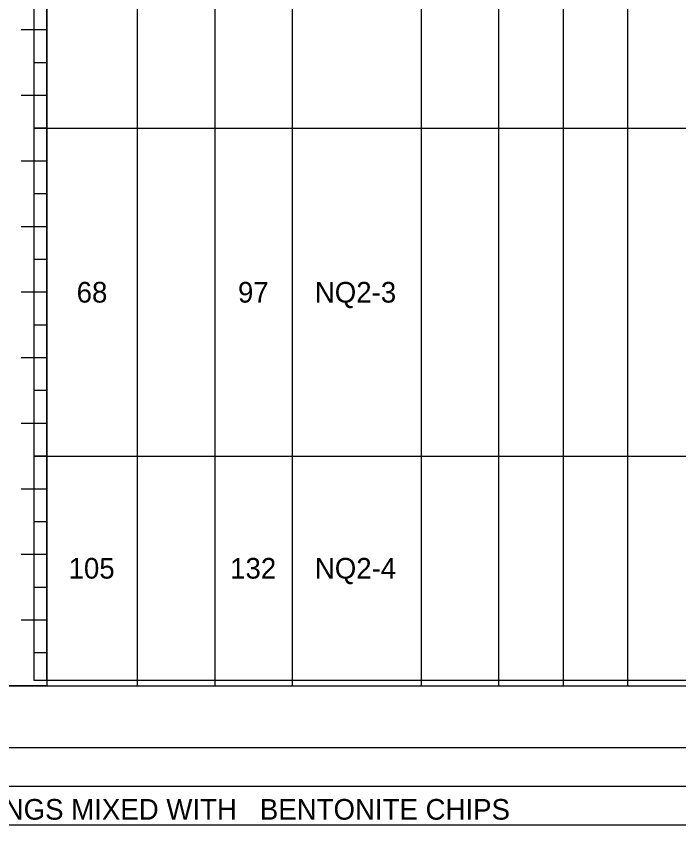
# Model space of a CAD drawing. Extents: x 0 to 0.833, y -0.32 to 0.608.
# Drawn here: x 0.4026 to 0.6165, y -0.32 to -0.0591 of the extents above; entities that cross this region are included whole.
import ezdxf

# ---------------------------------------------------------------- set-up
doc = ezdxf.new("R2010")
doc.units = 0

msp = doc.modelspace()

# ---------------------------------------------------------------- linework, layer by layer
for points in [[(0, -0.32004), (0.83333, -0.32004), (0.83333, 0.60833), (0, 0.60833)], [(0.40833, -0.09525), (0.4125, -0.09525), (0.4125, 0.01058), (0.40833, 0.01058)], [(0.40833, -0.20108), (0.4125, -0.20108), (0.4125, -0.09525), (0.40833, -0.09525)], [(0.40833, -0.2734), (0.4125, -0.2734), (0.4125, -0.20108), (0.40833, -0.20108)]]:
    msp.add_lwpolyline(points, close=True)
for points in [[(0.4125, 0.55417), (0.4125, -0.27517)], [(0.4125, 0.55417), (0.4125, -0.27517)], [(0.44167, 0.55417), (0.44167, -0.27517)], [(0.46667, 0.55417), (0.46667, -0.27517)], [(0.49167, 0.55417), (0.49167, -0.27517)], [(0.53333, 0.55417), (0.53333, -0.27517)], [(0.55833, 0.55417), (0.55833, -0.27517)], [(0.57917, 0.54167), (0.57917, -0.27517)], [(0.6, 0.54167), (0.6, -0.27517)], [(0.40833, 0.01058), (0.40833, -0.09525)], [(0.4125, -0.0635), (0.40417, -0.0635)], [(0.4125, -0.0635), (0.40833, -0.0635)], [(0.4125, -0.07408), (0.40833, -0.07408)], [(0.4125, -0.08467), (0.40417, -0.08467)], [(0.4125, -0.08467), (0.40833, -0.08467)], [(0.40833, -0.09525), (0.4125, -0.09525)], [(0.40833, -0.09525), (0.40833, -0.20108)], [(0.40833, -0.09525), (0.4125, -0.09525)], [(0.4125, -0.09525), (0.40833, -0.09525)], [(0.4125, -0.09525), (0.44167, -0.09525)], [(0.44167, -0.09525), (0.46667, -0.09525)], [(0.46667, -0.09525), (0.49167, -0.09525)], [(0.49167, -0.09525), (0.53333, -0.09525)], [(0.53333, -0.09525), (0.55833, -0.09525)], [(0.55833, -0.09525), (0.57917, -0.09525)], [(0.57917, -0.09525), (0.6, -0.09525)], [(0.6, -0.09525), (0.62083, -0.09525)], [(0.4125, -0.10583), (0.40417, -0.10583)], [(0.4125, -0.10583), (0.40833, -0.10583)], [(0.4125, -0.11642), (0.40833, -0.11642)], [(0.4125, -0.127), (0.40417, -0.127)], [(0.4125, -0.127), (0.40833, -0.127)], [(0.4125, -0.13758), (0.40833, -0.13758)], [(0.4125, -0.14817), (0.40417, -0.14817)], [(0.4125, -0.14817), (0.40833, -0.14817)], [(0.4125, -0.15875), (0.40833, -0.15875)], [(0.4125, -0.16933), (0.40417, -0.16933)], [(0.4125, -0.16933), (0.40833, -0.16933)], [(0.4125, -0.17992), (0.40833, -0.17992)], [(0.4125, -0.1905), (0.40417, -0.1905)], [(0.4125, -0.1905), (0.40833, -0.1905)], [(0.40833, -0.20108), (0.4125, -0.20108)], [(0.40833, -0.20108), (0.40833, -0.2734)], [(0.40833, -0.20108), (0.4125, -0.20108)], [(0.4125, -0.20108), (0.40833, -0.20108)], [(0.4125, -0.20108), (0.44167, -0.20108)], [(0.44167, -0.20108), (0.46667, -0.20108)], [(0.46667, -0.20108), (0.49167, -0.20108)], [(0.49167, -0.20108), (0.53333, -0.20108)], [(0.53333, -0.20108), (0.55833, -0.20108)], [(0.55833, -0.20108), (0.57917, -0.20108)], [(0.57917, -0.20108), (0.6, -0.20108)], [(0.6, -0.20108), (0.62083, -0.20108)], [(0, -0.20754), (0, -0.32004), (0.83333, -0.32004), (0.83333, -0.20754)], [(0.4125, -0.21167), (0.40417, -0.21167)], [(0.4125, -0.21167), (0.40833, -0.21167)], [(0.4125, -0.22225), (0.40833, -0.22225)], [(0.4125, -0.23283), (0.40417, -0.23283)], [(0.4125, -0.23283), (0.40833, -0.23283)], [(0.4125, -0.24342), (0.40833, -0.24342)], [(0.4125, -0.254), (0.40417, -0.254)], [(0.4125, -0.254), (0.40833, -0.254)], [(0.4125, -0.26458), (0.40833, -0.26458)], [(0.40833, -0.2734), (0.4125, -0.2734)], [(0.4125, -0.2734), (0.44167, -0.2734)], [(0.44167, -0.2734), (0.46667, -0.2734)], [(0.46667, -0.2734), (0.49167, -0.2734)], [(0.49167, -0.2734), (0.53333, -0.2734)], [(0.53333, -0.2734), (0.55833, -0.2734)], [(0.55833, -0.2734), (0.57917, -0.2734)], [(0.57917, -0.2734), (0.6, -0.2734)], [(0.6, -0.2734), (0.62083, -0.2734)], [(0.37917, -0.27517), (0.4125, -0.27517)], [(0.4125, -0.27517), (0.39583, -0.27517)], [(0.4125, -0.27517), (0.40417, -0.27517)], [(0.40833, -0.27517), (0.4125, -0.27517)], [(0.4125, -0.27517), (0.40833, -0.27517)], [(0.4125, -0.27517), (0.44167, -0.27517)], [(0.44167, -0.27517), (0.46667, -0.27517)], [(0.46667, -0.27517), (0.49167, -0.27517)], [(0.49167, -0.27517), (0.53333, -0.27517)], [(0.53333, -0.27517), (0.55833, -0.27517)], [(0.55833, -0.27517), (0.57917, -0.27517)], [(0.57917, -0.27517), (0.6, -0.27517)], [(0.6, -0.27517), (0.62083, -0.27517)], [(0, -0.29504), (0.83333, -0.29504)], [(0, -0.30754), (0.83333, -0.30754)]]:
    msp.add_lwpolyline(points)

# ---------------------------------------------------------------- texts
for s, height, p in [('68', 0.006667, (0.42211, -0.1515)), ('97', 0.006667, (0.4742, -0.1515)), ('NQ2-3', 0.006667, (0.499, -0.1515)), ('105', 0.006667, (0.4195, -0.24058)), ('132', 0.006667, (0.47165, -0.24058)), ('NQ2-4', 0.006667, (0.49901, -0.24058)), ('ASPHALT PATCH; AUGER CUTTINGS MIXED WITH   BENTONITE CHIPS', 0.0066667, (0.25986, -0.31838))]:
    msp.add_text(s, height=height).set_placement(p)

doc.saveas('drawing.dxf')
